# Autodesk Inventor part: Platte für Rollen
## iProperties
Created: 2010-08
Part Number: Platte für Rollen
Document SubType Name: Modeling
Designer: Administrator
Density: 1 g/cm^3
Author: Administrator
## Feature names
1. Extrusion1
2. Bohrung5 [Hole]
